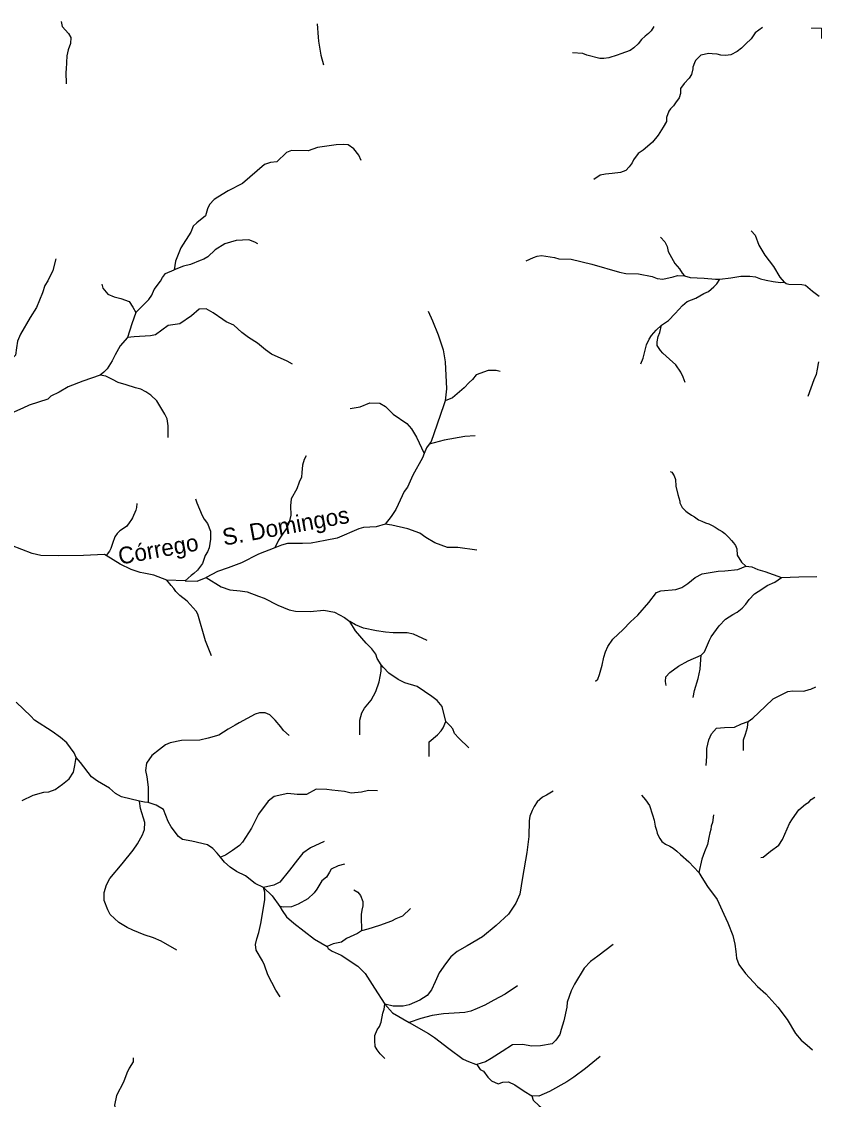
# Model space of a CAD drawing. Extents: x 717.8 to 772.7, y 8672.2 to 8728.
# Drawn here: x 763.19 to 772.73, y 8714.76 to 8727.61 of the extents above; entities that cross this region are included whole.
import ezdxf
from ezdxf.enums import TextEntityAlignment as Align

# ---------------------------------------------------------------- set-up
doc = ezdxf.new("R2010")
doc.units = 0
doc.header["$LTSCALE"] = 0.08
doc.linetypes.add('LONG_DASHED', pattern=[7.5, 6, -1.5])
doc.layers.add('61', color=7, linetype='Continuous')
doc.layers.add('63', color=7, linetype='Continuous', lineweight=13)
doc.layers.add('9', color=7, linetype='LONG_DASHED', lineweight=25)

msp = doc.modelspace()

# ---------------------------------------------------------------- linework, layer by layer
at = {"layer": '63'}
msp.add_lwpolyline([(772.73, 8727.4098), (772.73, 8727.533), (772.6086, 8727.533)], dxfattribs=at)
at = {"layer": '9'}
for p, q in [((765.1398, 8720.9427), (764.9225, 8720.9473)), ((771.4443, 8718.1485), (771.4292, 8718.0588))]:
    msp.add_line(p, q, dxfattribs=at)
for points in [[(763.6608, 8727.611), (763.6724, 8727.5514), (763.7475, 8727.4677), (763.7777, 8727.422), (763.7723, 8727.3508), (763.746, 8727.2757), (763.7274, 8727.2014), (763.722, 8727.0442), (763.7173, 8727.0055), (763.722, 8726.8701)], [(766.7165, 8727.5851), (766.725, 8727.4264), (766.7296, 8727.3768), (766.7466, 8727.2824), (766.7599, 8727.2088), (766.7924, 8727.0949)], [(770.7317, 8727.551), (770.6984, 8727.5018), (770.6656, 8727.4692), (770.6268, 8727.4365), (770.5855, 8727.3967), (770.5436, 8727.3458), (770.4933, 8727.2963), (770.4476, 8727.2653), (770.3911, 8727.2451), (770.3362, 8727.2266), (770.2936, 8727.2111), (770.1941, 8727.1796), (770.1326, 8727.1693), (770.0869, 8727.1685), (769.9315, 8727.2087), (769.8825, 8727.2281), (769.7595, 8727.2374)], [(772.0259, 8727.5393), (771.9384, 8727.4766), (771.8904, 8727.4038), (771.8266, 8727.3444), (771.7751, 8727.2923), (771.7256, 8727.2536), (771.6489, 8727.2157), (771.5839, 8727.2048), (771.5305, 8727.2111), (771.4864, 8727.222), (771.426, 8727.2274)], [(771.426, 8727.2274), (771.3857, 8727.2289), (771.2913, 8727.2088), (771.2585, 8727.1792), (771.2286, 8727.1484), (771.2171, 8727.1202), (771.1975, 8727.0678)], [(771.1975, 8727.0678), (771.1944, 8727.0454), (771.1797, 8726.9788), (771.1541, 8726.9346), (771.0938, 8726.8712), (771.0504, 8726.8108), (771.0473, 8726.7535), (771.0326, 8726.7008), (770.9901, 8726.6412), (770.9634, 8726.6053), (770.9283, 8726.5705), (770.9082, 8726.5406), (770.8834, 8726.4658), (770.8836, 8726.4209), (770.8435, 8726.3512), (770.7841, 8726.2571), (770.7167, 8726.1727), (770.6279, 8726.0972), (770.6028, 8726.0772), (770.5426, 8726.0375), (770.4875, 8725.9628), (770.4729, 8725.928), (770.4381, 8725.8792), (770.3955, 8725.8358), (770.332, 8725.8102), (770.2322, 8725.8009), (770.1524, 8725.7916), (770.0905, 8725.7777), (770.0131, 8725.7289)], [(767.2389, 8725.9526), (767.2115, 8726.0177), (767.154, 8726.0918), (767.0846, 8726.139), (767.0246, 8726.1455), (766.9421, 8726.1423), (766.7178, 8726.1098), (766.6083, 8726.0674), (766.4092, 8726.074), (766.35, 8726.0489), (766.232, 8725.9385), (766.1569, 8725.9301), (766.0883, 8725.9078), (765.8261, 8725.6793), (765.6522, 8725.5923), (765.5317, 8725.5179), (765.4855, 8725.4875), (765.4317, 8725.4299), (765.4071, 8725.379), (765.3835, 8725.2921), (765.2797, 8725.2109), (765.2373, 8725.1721), (765.2073, 8725.1001), (765.087, 8724.9129), (765.0256, 8724.7529), (765.0108, 8724.6494)], [(770.8111, 8725.0415), (770.8608, 8724.9851), (770.8917, 8724.9267), (770.9035, 8724.8706), (770.9209, 8724.8323), (770.9816, 8724.7268), (771.038, 8724.6636), (771.0698, 8724.6095), (771.097, 8724.5782)], [(771.8916, 8725.1148), (771.9376, 8725.0621), (771.9836, 8724.9449), (772.0541, 8724.8252), (772.1565, 8724.6895), (772.235, 8724.5607), (772.2853, 8724.5029)], [(766.0087, 8724.9592), (765.972, 8724.9815), (765.8987, 8725.0059), (765.7484, 8725.0002), (765.6147, 8724.9621), (765.4989, 8724.888), (765.4105, 8724.8068), (765.3619, 8724.7783), (765.3214, 8724.7622), (765.2042, 8724.7126), (765.1191, 8724.6936), (765.0108, 8724.6494)], [(763.5982, 8724.7803), (763.5611, 8724.6423), (763.5026, 8724.5196), (763.4686, 8724.4639), (763.4394, 8724.3752), (763.3687, 8724.2027), (763.2936, 8724.0797), (763.176, 8723.8834), (763.1407, 8723.7986), (763.129, 8723.7209), (763.1181, 8723.6332), (762.9961, 8723.5095), (762.9156, 8723.3784), (762.8687, 8723.2762), (762.836, 8723.1411), (762.7934, 8723.0515), (762.7274, 8722.9371), (762.6587, 8722.8609)], [(769.2075, 8724.759), (769.2966, 8724.7958), (769.3394, 8724.8133), (769.39, 8724.8224), (769.5464, 8724.7978), (769.5973, 8724.7831), (769.7432, 8724.7758), (769.991, 8724.7169), (770.321, 8724.6235), (770.3978, 8724.6065), (770.548, 8724.6007), (770.7093, 8724.5706), (770.7705, 8724.5468), (770.8387, 8724.5387), (770.9594, 8724.5672), (771.0129, 8724.5832), (771.097, 8724.5782)], [(764.5508, 8724.1401), (764.6489, 8724.2363), (764.7063, 8724.2955), (764.7419, 8724.3467), (764.7693, 8724.4159), (764.8475, 8724.5141), (764.8703, 8724.5582), (764.9067, 8724.6069), (765.0108, 8724.6494)], [(770.8213, 8723.9907), (770.9062, 8724.0455), (770.9856, 8724.131), (771.0723, 8724.2261), (771.1289, 8724.2707), (771.2318, 8724.3134), (771.3257, 8724.3688), (771.3822, 8724.3917), (771.4471, 8724.4466), (771.4825, 8724.4813), (771.516, 8724.5396)], [(771.097, 8724.5782), (771.1638, 8724.5581), (771.3301, 8724.5498), (771.4666, 8724.5395), (771.516, 8724.5396)], [(771.516, 8724.5396), (771.6488, 8724.5541), (771.7702, 8724.5737), (771.8768, 8724.5764), (771.9418, 8724.5677), (772.0044, 8724.541), (772.0717, 8724.5255), (772.1539, 8724.5108), (772.24, 8724.5005), (772.2853, 8724.5029)], [(772.7017, 8724.3333), (772.6219, 8724.3904), (772.538, 8724.4625), (772.4974, 8724.4726), (772.3424, 8724.4741), (772.3078, 8724.4849), (772.2853, 8724.5029)], [(764.1467, 8724.4786), (764.1591, 8724.4327), (764.2199, 8724.3607), (764.2918, 8724.3272), (764.3725, 8724.3073), (764.4733, 8724.2721), (764.5174, 8724.2064), (764.5508, 8724.1401)], [(766.4193, 8723.5257), (766.3577, 8723.5626), (766.1721, 8723.6451), (766.1005, 8723.6966), (766.005, 8723.7736), (765.8949, 8723.8414), (765.8171, 8723.9038), (765.723, 8723.9899), (765.6277, 8724.03), (765.59, 8724.0569), (765.473, 8724.1378), (765.3921, 8724.1864), (765.3069, 8724.1825), (765.2158, 8724.1008), (765.0771, 8724.0069), (764.9362, 8723.9861), (764.7865, 8723.8744), (764.7263, 8723.8624), (764.5336, 8723.8506), (764.4513, 8723.8429)], [(764.5508, 8724.1401), (764.5061, 8724.0067), (764.4513, 8723.8429)], [(768.0373, 8724.1569), (768.0926, 8724.0401), (768.1594, 8723.8752), (768.2168, 8723.6978), (768.2435, 8723.5544), (768.2593, 8723.2309), (768.2417, 8723.0897)], [(770.5745, 8723.5294), (770.6017, 8723.5981), (770.6439, 8723.7559), (770.677, 8723.8227), (770.7047, 8723.8684), (770.76, 8723.9316), (770.8213, 8723.9907)], [(771.1037, 8723.3068), (771.0825, 8723.3705), (771.0533, 8723.4316), (770.9922, 8723.5153), (770.9183, 8723.5837), (770.8388, 8723.6577), (770.8088, 8723.6866), (770.7721, 8723.7468), (770.769, 8723.7913), (770.7841, 8723.8546), (770.804, 8723.9033), (770.8213, 8723.9907)], [(764.4513, 8723.8429), (764.3649, 8723.7438), (764.3048, 8723.6357), (764.2686, 8723.5637), (764.2085, 8723.4711), (764.171, 8723.4286), (764.1283, 8723.3948)], [(772.6952, 8723.5516), (772.6909, 8723.5324), (772.6799, 8723.4672), (772.6651, 8723.4022), (772.6394, 8723.337), (772.5693, 8723.1393)], [(764.1283, 8723.3948), (763.9194, 8723.3238), (763.7448, 8723.2539), (763.6375, 8723.1892), (763.538, 8723.1429), (763.5043, 8723.1083), (763.2782, 8723.0347), (763.2029, 8723.001), (763.0692, 8722.9417), (763.0088, 8722.9221), (762.7509, 8722.8653), (762.6587, 8722.8609)], [(764.939, 8722.6492), (764.9376, 8722.738), (764.9376, 8722.7887), (764.9274, 8722.8717), (764.8964, 8722.9293), (764.8017, 8723.089), (764.7316, 8723.1563), (764.6695, 8723.1944), (764.6133, 8723.2256), (764.5479, 8723.2442), (764.4353, 8723.277), (764.3414, 8723.3071), (764.2735, 8723.3438), (764.1936, 8723.3838), (764.1283, 8723.3948)], [(768.8962, 8723.4357), (768.8496, 8723.449), (768.7529, 8723.4483), (768.6115, 8723.3963), (768.5688, 8723.3416), (768.5284, 8723.3058), (768.4688, 8723.2419), (768.3305, 8723.1226), (768.2417, 8723.0897)], [(768.2417, 8723.0897), (768.2259, 8723.041), (768.1048, 8722.6926), (768.0732, 8722.6043), (768.0513, 8722.5707)], [(767.1096, 8722.9976), (767.2281, 8723.0143), (767.3414, 8723.0623), (767.4617, 8723.0617), (767.5296, 8723.0194), (767.6211, 8722.9289), (767.7833, 8722.8171), (767.8412, 8722.7519), (767.8996, 8722.6564), (767.9919, 8722.4609)], [(768.0513, 8722.5707), (768.0191, 8722.5261), (767.9919, 8722.4609)], [(768.5995, 8722.6704), (768.4766, 8722.6638), (768.2279, 8722.6184), (768.0513, 8722.5707)], [(767.9919, 8722.4609), (767.9717, 8722.4096), (767.8568, 8722.2017), (767.7924, 8722.059), (767.7531, 8722.0072), (767.6804, 8721.8509), (767.6539, 8721.7907), (767.5957, 8721.7065), (767.5242, 8721.616)], [(766.5825, 8722.4313), (766.558, 8722.3876), (766.5384, 8722.3198), (766.5333, 8722.2324), (766.5284, 8722.1791), (766.4991, 8722.1159), (766.4724, 8722.0377), (766.406, 8721.92), (766.3955, 8721.8355), (766.401, 8721.7229), (766.3814, 8721.6403), (766.3521, 8721.5724), (766.2837, 8721.4753), (766.2545, 8721.4268), (766.2097, 8721.3366)], [(770.9248, 8722.2458), (770.9455, 8722.2374), (770.9746, 8722.1937), (770.9907, 8722.1477), (770.9923, 8722.07), (771.0168, 8721.9706), (771.0397, 8721.8899)], [(764.566, 8721.8641), (764.5614, 8721.8174), (764.5515, 8721.7854), (764.5118, 8721.6932), (764.4985, 8721.6735), (764.4722, 8721.6339), (764.439, 8721.5879), (764.3632, 8721.5385), (764.3301, 8721.5056), (764.3004, 8721.466), (764.2739, 8721.3871), (764.2541, 8721.3277), (764.2375, 8721.2948), (764.1998, 8721.2416)], [(765.2648, 8721.9204), (765.2781, 8721.8709), (765.3438, 8721.7194), (765.3669, 8721.6765), (765.4064, 8721.6239), (765.4426, 8721.5349), (765.4424, 8721.4393), (765.4258, 8721.334), (765.4059, 8721.2879), (765.3795, 8721.2417), (765.3464, 8721.1494), (765.2874, 8721.0677), (765.2442, 8721.0304), (765.2109, 8721.0045), (765.1398, 8720.9427)], [(771.0397, 8721.8899), (771.0405, 8721.8725), (771.0696, 8721.8143), (771.1133, 8721.7706), (771.1275, 8721.7582), (771.1787, 8721.7256), (771.2166, 8721.7026), (771.2654, 8721.6688), (771.3021, 8721.6531), (771.3485, 8721.6314), (771.3864, 8721.6193), (771.4268, 8721.6023), (771.4635, 8721.583), (771.5112, 8721.5492), (771.5453, 8721.531), (771.5772, 8721.5045), (771.6028, 8721.4802), (771.626, 8721.456), (771.6566, 8721.4234), (771.6798, 8721.3944), (771.703, 8721.3618), (771.7201, 8721.3207), (771.7231, 8721.2483)], [(767.5242, 8721.616), (767.4193, 8721.5839), (767.2665, 8721.5774), (767.2104, 8721.561), (766.953, 8721.4501), (766.8114, 8721.4212), (766.6449, 8721.3913), (766.54, 8721.3877), (766.3622, 8721.3852), (766.2908, 8721.3665), (766.2097, 8721.3366)], [(768.6204, 8721.3049), (768.3913, 8721.3367), (768.2691, 8721.3399), (768.1175, 8721.3945), (768.0116, 8721.4581), (767.9408, 8721.5078), (767.7972, 8721.5625), (767.6044, 8721.6041), (767.5242, 8721.616)], [(764.1998, 8721.2416), (764.1772, 8721.2557), (763.9262, 8721.2425), (763.6307, 8721.2394), (763.42, 8721.2413), (763.3165, 8721.2658), (763.0705, 8721.3606)], [(766.2097, 8721.3366), (766.0169, 8721.2594), (765.8117, 8721.1563), (765.6552, 8721.0973), (765.5257, 8721.0511), (765.3927, 8720.9805)], [(764.9225, 8720.9473), (764.7667, 8721.0089), (764.6459, 8721.0327), (764.6019, 8721.0408), (764.4972, 8721.0763), (764.3635, 8721.1392), (764.1998, 8721.2416)], [(771.7231, 8721.2483), (771.7751, 8721.1617), (771.8269, 8721.1161)], [(770.0333, 8719.7449), (770.0608, 8719.7695), (770.0844, 8719.8255), (770.1158, 8719.9356), (770.1335, 8720.03), (770.1532, 8720.0939), (770.1806, 8720.1589), (770.2425, 8720.2473), (770.3644, 8720.3624), (770.4509, 8720.4538), (770.5383, 8720.5311), (770.6722, 8720.6835), (770.7641, 8720.8015), (770.8126, 8720.8227), (770.9944, 8720.8364), (771.0642, 8720.862), (771.135, 8720.9089), (771.2254, 8720.979), (771.307, 8721.0242), (771.4984, 8721.0546), (771.5792, 8721.0612), (771.7336, 8721.0761), (771.8269, 8721.1161)], [(771.8269, 8721.1161), (771.8999, 8721.1091), (771.97, 8721.0759), (772.0549, 8721.0526), (772.2542, 8720.9816)], [(765.4564, 8720.0464), (765.3839, 8720.2246), (765.2935, 8720.5425), (765.2707, 8720.5804), (765.1629, 8720.6986), (765.0774, 8720.7645), (765.0274, 8720.8136), (765.0046, 8720.8489), (764.9721, 8720.8863), (764.9225, 8720.9473)], [(765.1398, 8720.9427), (765.2838, 8720.9357), (765.3927, 8720.9805)], [(765.3927, 8720.9805), (765.5684, 8720.8691), (765.6718, 8720.8353), (765.7966, 8720.8237), (765.8793, 8720.8085), (766.0151, 8720.7582), (766.0833, 8720.7347), (766.2466, 8720.6499), (766.381, 8720.5955), (766.4548, 8720.5785), (766.6303, 8720.5768), (766.7951, 8720.591), (766.9218, 8720.566), (767.0418, 8720.5035), (767.1056, 8720.4546)], [(771.294, 8720.0548), (771.3357, 8720.0944), (771.3931, 8720.2344), (771.415, 8720.2733), (771.5095, 8720.4058), (771.5862, 8720.4846), (771.6715, 8720.5383), (771.7259, 8720.5693), (771.7863, 8720.6164), (771.8279, 8720.6611), (771.8687, 8720.72), (771.9315, 8720.7852), (772.017, 8720.8409), (772.0808, 8720.8844), (772.175, 8720.9258), (772.2542, 8720.9816)], [(772.2542, 8720.9816), (772.4584, 8720.9886), (772.6739, 8720.9943)], [(768.0271, 8720.2314), (767.8625, 8720.304), (767.7892, 8720.3203), (767.623, 8720.3203), (767.5314, 8720.3294), (767.4208, 8720.344), (767.2676, 8720.3766), (767.1708, 8720.4165), (767.1056, 8720.4546)], [(767.4803, 8719.938), (767.4317, 8720.0151), (767.4145, 8720.0657), (767.3687, 8720.1311), (767.3009, 8720.1995), (767.1727, 8720.3463), (767.1056, 8720.4546)], [(770.8783, 8719.6947), (770.8681, 8719.7387), (770.8736, 8719.7944), (770.9223, 8719.8486), (771.0259, 8719.9221), (771.1396, 8719.9869), (771.294, 8720.0548)], [(771.2006, 8719.5491), (771.215, 8719.6336), (771.2612, 8719.7771), (771.2816, 8719.8856), (771.2927, 8720.0016), (771.294, 8720.0548)], [(767.225, 8719.1051), (767.2239, 8719.2774), (767.2484, 8719.3658), (767.2788, 8719.4205), (767.3586, 8719.5198), (767.4135, 8719.6208), (767.4543, 8719.735), (767.479, 8719.8642), (767.4803, 8719.938)], [(768.2491, 8719.2643), (768.2041, 8719.4411), (768.1448, 8719.5131), (768.0844, 8719.5628), (767.9076, 8719.6798), (767.7616, 8719.7254), (767.6807, 8719.765), (767.5707, 8719.8416), (767.508, 8719.9086), (767.4803, 8719.938)], [(771.8543, 8719.2649), (771.91, 8719.3017), (772.0577, 8719.4423), (772.1553, 8719.5323), (772.3287, 8719.6211), (772.3899, 8719.6278), (772.5202, 8719.6255), (772.5831, 8719.644), (772.6046, 8719.6507), (772.6615, 8719.6762)], [(763.839, 8718.8338), (763.8154, 8718.891), (763.7298, 8719.0071), (763.6531, 8719.0739), (763.5525, 8719.1443), (763.3434, 8719.2806), (763.2997, 8719.3269), (763.1251, 8719.4955)], [(766.3824, 8719.0977), (766.3142, 8719.1543), (766.2801, 8719.2008), (766.2141, 8719.2806), (766.1516, 8719.3423), (766.0929, 8719.3656), (766.0283, 8719.3656), (765.977, 8719.3502), (765.783, 8719.248), (765.7358, 8719.2211), (765.6546, 8719.1711), (765.5406, 8719.1014), (765.4158, 8719.0658), (765.3142, 8719.0418), (765.0987, 8719.0353), (764.9623, 8719.0092), (764.9071, 8718.9845), (764.8333, 8718.9293), (764.7416, 8718.8581), (764.6807, 8718.7673), (764.6676, 8718.6773), (764.685, 8718.6025), (764.6981, 8718.4791), (764.6992, 8718.2966)], [(768.0497, 8718.8474), (768.0503, 8719.0218), (768.1496, 8719.1045), (768.1942, 8719.1509), (768.2174, 8719.1872), (768.2491, 8719.2643)], [(768.5237, 8718.9486), (768.4042, 8719.0646), (768.3548, 8719.1218), (768.3322, 8719.1777), (768.3001, 8719.2098), (768.2491, 8719.2643)], [(771.353, 8718.7393), (771.3616, 8718.8468), (771.3645, 8718.9406), (771.3881, 8719.0445), (771.4199, 8719.1173), (771.4767, 8719.1842), (771.5751, 8719.1901), (771.6926, 8719.1958), (771.7745, 8719.2368), (771.8543, 8719.2649)], [(771.7993, 8718.9178), (771.7986, 8719.0439), (771.8258, 8719.1134), (771.8489, 8719.1904), (771.8543, 8719.2649)], [(763.1969, 8718.3216), (763.3288, 8718.3833), (763.453, 8718.4203), (763.513, 8718.4246), (763.5913, 8718.4533), (763.6768, 8718.5153), (763.7582, 8718.5779), (763.8079, 8718.6585), (763.8242, 8718.7382), (763.839, 8718.8338)], [(764.5963, 8718.3153), (764.3802, 8718.3644), (764.3081, 8718.4064), (764.2379, 8718.468), (764.095, 8718.5536), (764.0246, 8718.6052), (763.8902, 8718.7734), (763.839, 8718.8338)], [(767.4347, 8718.4362), (767.3254, 8718.439), (767.2427, 8718.4215), (767.1205, 8718.4096), (767.0406, 8718.4279), (766.89, 8718.4426), (766.8284, 8718.4536), (766.7035, 8718.4545), (766.5868, 8718.392), (766.4766, 8718.393), (766.3646, 8718.4031), (766.2002, 8718.3691), (766.1313, 8718.313), (766.0157, 8718.1594), (765.9318, 8717.991), (765.8229, 8717.8238), (765.7871, 8717.7834), (765.7035, 8717.7263), (765.6206, 8717.6711), (765.5616, 8717.6452)], [(769.5289, 8718.434), (769.4524, 8718.3846), (769.4017, 8718.3612), (769.3377, 8718.3055), (769.3016, 8718.2517), (769.2809, 8718.2008), (769.2503, 8718.1345), (769.2443, 8718.0782), (769.24, 8717.8919), (769.2166, 8717.6995), (769.1657, 8717.4049), (769.1338, 8717.2061), (769.0859, 8717.0977), (768.9967, 8716.9653), (768.85, 8716.8288), (768.687, 8716.6973), (768.5054, 8716.5873), (768.3851, 8716.519), (768.3092, 8716.455), (768.2461, 8716.3714), (768.1689, 8716.2678), (768.1238, 8716.1596), (768.0781, 8716.0635), (768.0275, 8715.9945), (767.9408, 8715.9398), (767.8112, 8715.8826), (767.7412, 8715.8681), (767.6216, 8715.8688), (767.5221, 8715.8911)], [(770.5818, 8718.3855), (770.6326, 8718.3289), (770.6807, 8718.2612), (770.7167, 8718.1486), (770.7356, 8718.0859)], [(772.0068, 8717.6397), (772.0338, 8717.6464), (772.123, 8717.716), (772.2215, 8717.789), (772.2653, 8717.8552), (772.3504, 8718.0477), (772.3863, 8718.1024), (772.4592, 8718.2098), (772.5389, 8718.276), (772.5781, 8718.2997), (772.6076, 8718.3325), (772.6496, 8718.3604)], [(765.0404, 8716.5369), (764.853, 8716.6451), (764.7618, 8716.6825), (764.6521, 8716.72), (764.5163, 8716.7752), (764.4471, 8716.8063), (764.3474, 8716.8664), (764.2442, 8716.962), (764.2174, 8717.0179), (764.1763, 8717.1296), (764.175, 8717.2244), (764.2004, 8717.3163), (764.2407, 8717.3927), (764.3878, 8717.5667), (764.5207, 8717.7308), (764.5707, 8717.8048), (764.6302, 8717.9117), (764.6536, 8717.9739), (764.6578, 8718.0609), (764.6087, 8718.2272), (764.5963, 8718.3153)], [(764.6992, 8718.2966), (764.6557, 8718.3016), (764.5963, 8718.3153)], [(765.5616, 8717.6452), (765.5215, 8717.694), (765.4688, 8717.748), (765.405, 8717.7907), (765.2205, 8717.8357), (765.1081, 8717.8554), (765.0608, 8717.8929), (764.9731, 8718.0082), (764.9367, 8718.0703), (764.8816, 8718.2122), (764.7948, 8718.2675), (764.6992, 8718.2966)], [(770.7356, 8718.0859), (770.7459, 8718.0169), (770.7608, 8717.9686), (770.7706, 8717.9335), (770.7771, 8717.9122), (770.8036, 8717.8688), (770.8274, 8717.8312), (770.8687, 8717.7992), (770.921, 8717.7778), (770.9601, 8717.754)], [(771.4292, 8718.0588), (771.416, 8718.0139), (771.4092, 8717.9754), (771.3986, 8717.9341), (771.3853, 8717.882), (771.3707, 8717.7954), (771.3331, 8717.7084)], [(766.7969, 8717.8324), (766.6363, 8717.755), (766.5448, 8717.6944), (766.4816, 8717.6142), (766.3868, 8717.4886), (766.2705, 8717.3476), (766.1985, 8717.3134), (766.0742, 8717.2851)], [(770.9601, 8717.754), (771.0066, 8717.7186), (771.0506, 8717.6779), (771.1489, 8717.5895), (771.2691, 8717.463)], [(771.3331, 8717.7084), (771.3052, 8717.6201), (771.2691, 8717.463)], [(766.0742, 8717.2851), (765.9771, 8717.3297), (765.8587, 8717.4213), (765.7524, 8717.4763), (765.6783, 8717.5282), (765.6111, 8717.5871), (765.5616, 8717.6452)], [(767.0428, 8717.562), (766.9663, 8717.542), (766.8813, 8717.5031), (766.8636, 8717.4685), (766.8245, 8717.4068), (766.7696, 8717.3645), (766.7121, 8717.265), (766.6792, 8717.2185), (766.6033, 8717.1491), (766.4873, 8717.084), (766.408, 8717.0537), (766.3109, 8717.0476), (766.2716, 8717.0586)], [(771.2691, 8717.463), (771.3013, 8717.4048), (771.3701, 8717.2959), (771.4857, 8717.139), (771.5666, 8716.9667), (771.614, 8716.8619), (771.6747, 8716.7095), (771.6975, 8716.6076), (771.7085, 8716.5185), (771.7153, 8716.4405), (771.7449, 8716.3659), (771.8255, 8716.2599), (771.9662, 8716.1013), (772.0679, 8716.014), (772.2094, 8715.8571), (772.323, 8715.7112), (772.4204, 8715.5409), (772.4882, 8715.4637), (772.5586, 8715.4026), (772.6235, 8715.3469)], [(766.2746, 8715.9815), (766.2213, 8716.0596), (766.1258, 8716.2406), (766.0852, 8716.359), (766.0622, 8716.4104), (765.9878, 8716.5363), (765.9777, 8716.6052), (765.9949, 8716.6733), (766.0189, 8716.7455), (766.0428, 8716.8537), (766.0901, 8717.1357), (766.0917, 8717.2286), (766.0742, 8717.2851)], [(766.0742, 8717.2851), (766.18, 8717.1844), (766.2716, 8717.0586)], [(767.1508, 8717.2542), (767.1999, 8717.2285), (767.2304, 8717.1864), (767.261, 8717.1185), (767.2588, 8717.0646), (767.2496, 8717.013), (767.2404, 8716.9615), (767.2406, 8716.8796), (767.2443, 8716.8321), (767.2456, 8716.7666)], [(766.2716, 8717.0586), (766.2968, 8717.0091), (766.3504, 8716.9337), (766.4349, 8716.8574), (766.6846, 8716.6674), (766.8356, 8716.5797)], [(767.8265, 8717.0344), (767.7335, 8716.941), (767.652, 8716.9085), (767.5997, 8716.8837), (767.4573, 8716.8322), (767.3177, 8716.7881), (767.2456, 8716.7666)], [(767.2456, 8716.7666), (767.1942, 8716.7347), (767.0663, 8716.6762), (767.0037, 8716.6327), (766.9057, 8716.6116), (766.8356, 8716.5797)], [(766.8356, 8716.5797), (766.8479, 8716.5571), (766.8948, 8716.5231), (767.002, 8716.4765), (767.1996, 8716.3453), (767.2875, 8716.258), (767.3992, 8716.0822), (767.5221, 8715.8911)], [(770.2455, 8716.6024), (770.0611, 8716.4658), (769.9757, 8716.4006), (769.8996, 8716.3233), (769.7855, 8716.1295), (769.7461, 8716.0515), (769.6977, 8715.916), (769.6925, 8715.856), (769.6582, 8715.692), (769.6259, 8715.5893), (769.6081, 8715.5302), (769.5622, 8715.4631), (769.5176, 8715.4176), (769.38, 8715.3951), (769.2702, 8715.3914), (769.1676, 8715.4104), (769.0434, 8715.406), (768.9221, 8715.3276), (768.7887, 8715.2424), (768.7241, 8715.2065), (768.619, 8715.1716)], [(769.1032, 8716.1125), (768.9557, 8716.0114), (768.823, 8715.9389), (768.7145, 8715.8786), (768.6252, 8715.8421), (768.5488, 8715.8074), (768.4755, 8715.7935), (768.3511, 8715.7852), (768.2223, 8715.777), (768.0875, 8715.7571), (767.9515, 8715.7225), (767.8138, 8715.6738)], [(767.4768, 8715.6762), (767.5, 8715.7859), (767.5124, 8715.8333), (767.5221, 8715.8911)], [(767.5221, 8715.8911), (767.6142, 8715.7879), (767.8138, 8715.6738)], [(767.5222, 8715.2452), (767.4655, 8715.2995), (767.4323, 8715.3487), (767.4084, 8715.3862), (767.4011, 8715.4596), (767.4033, 8715.5182), (767.4313, 8715.5853), (767.458, 8715.6263), (767.4768, 8715.6762)], [(767.8138, 8715.6738), (768.0436, 8715.544), (768.1165, 8715.4933), (768.2853, 8715.3626), (768.4557, 8715.2382), (768.5198, 8715.2085), (768.603, 8715.1777), (768.619, 8715.1716)], [(764.5192, 8715.2515), (764.5185, 8715.2032), (764.4721, 8715.1288), (764.4428, 8715.0696), (764.4066, 8714.9641), (764.3225, 8714.8019), (764.2985, 8714.6894), (764.3118, 8714.5965), (764.3289, 8714.5119), (764.3629, 8714.4431), (764.4512, 8714.3153), (764.4779, 8714.2803), (764.4754, 8714.1773), (764.4601, 8714.1315), (764.4347, 8714.0806), (764.4118, 8714.0011), (764.3889, 8713.9407), (764.3489, 8713.8619), (764.2896, 8713.7995), (764.2849, 8713.7937)], [(770.092, 8715.2692), (769.9149, 8715.1256), (769.7755, 8715.0215), (769.6941, 8714.9676), (769.4853, 8714.8494), (769.3573, 8714.7957), (769.2741, 8714.7978)], [(768.619, 8715.1716), (768.6611, 8715.1138), (768.6998, 8715.0917), (768.7527, 8715.022), (768.7938, 8714.9793), (768.8757, 8714.9442), (768.9293, 8714.9627), (768.9956, 8714.9655), (769.0739, 8714.9286), (769.1853, 8714.8531), (769.2741, 8714.7978)], [(769.2741, 8714.7978), (769.2934, 8714.7462), (769.365, 8714.681), (769.4869, 8714.5889), (769.5515, 8714.5358), (769.6286, 8714.4991), (769.6774, 8714.4999), (769.7412, 8714.4672), (769.7874, 8714.4478), (769.8596, 8714.4386)]]:
    msp.add_lwpolyline(points, dxfattribs=at)

# ---------------------------------------------------------------- texts
at = {"layer": '61'}
msp.add_text('Córrego    S. Domingos', height=0.2, rotation=10.34, dxfattribs=at).set_placement((765.736, 8721.3839), align=Align.CENTER)

doc.saveas('drawing.dxf')
